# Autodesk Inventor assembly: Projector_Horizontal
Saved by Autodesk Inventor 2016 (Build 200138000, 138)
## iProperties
Created: 2015-11
Part Number: Projector_Horizontal
Document SubType Name: Assembly
Designer: John
Author: John
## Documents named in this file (4)
- D:\3D Printer Designs\John Ledden Designs\DLP Printer\V0-4\Projector_Horizontal.iam
- D:\3D Printer Designs\John Ledden Designs\DLP Printer\V0-4\Acer_Projector.ipt
- D:\3D Printer Designs\John Ledden Designs\DLP Printer\V0-4\Frame_ProjectorMount_H.ipt
- D:\3D Printer Designs\John Ledden Designs\DLP Printer\V0-4\Projector_Horizontal.ipt
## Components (3 placed, 3 different names)
1. Acer_Projector_1008
2. Frame_ProjectorMount_H_1009
3. Projector_Horizontal
